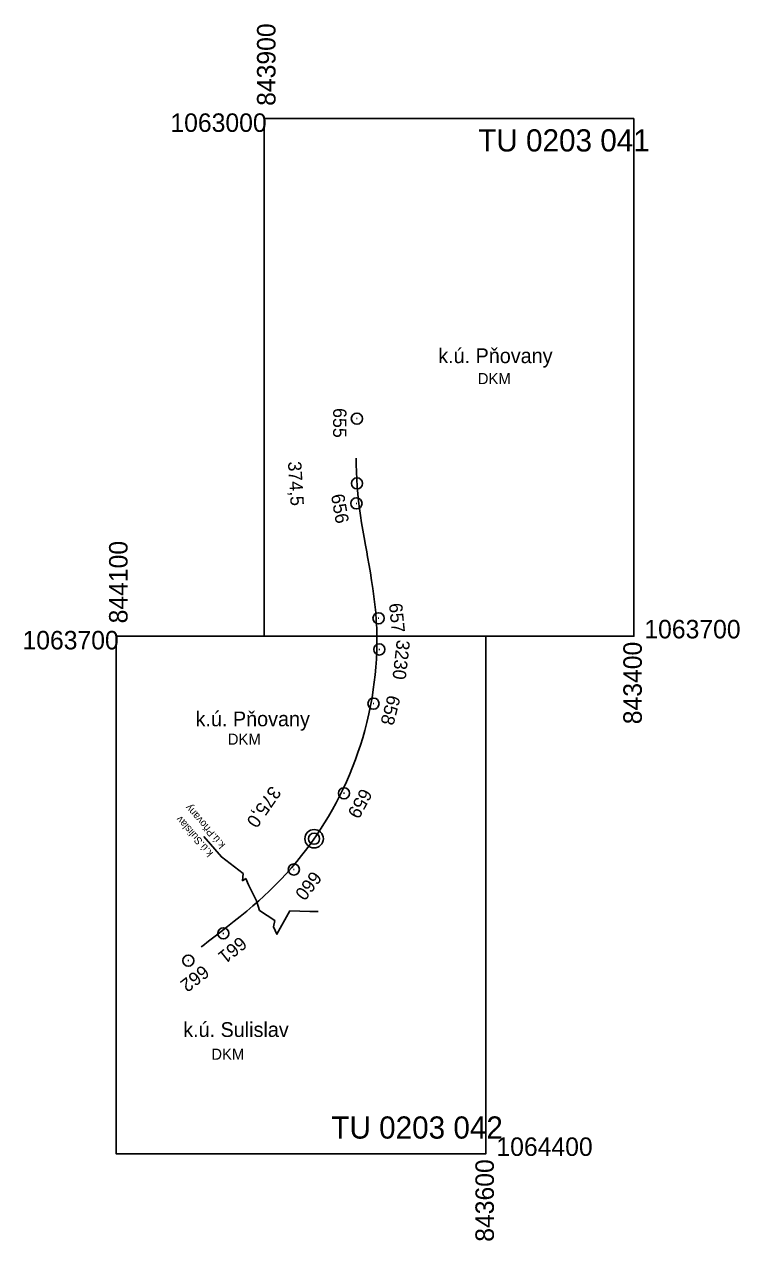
# Model space of a CAD drawing. Extents: x -867628 to -843257, y -1065611 to -1039859.
# Drawn here: x -844224 to -843257, y -1064518 to -1062872 of the extents above; entities that cross this region are included whole.
import ezdxf

# ---------------------------------------------------------------- set-up
doc = ezdxf.new("R2010")
doc.units = 0
for name, color, linetype in [('Vrstva 1', 7, 'Continuous'), ('Vrstva 10', 7, 'Continuous'), ('Vrstva 55', 7, 'Continuous'), ('Vrstva 62', 7, 'Continuous'), ('Vrstva 63', 7, 'Continuous'), ('Vrstva 7', 7, 'Continuous')]:
    doc.layers.add(name, color=color, linetype=linetype)

msp = doc.modelspace()

# ---------------------------------------------------------------- linework, layer by layer
at = {"layer": 'Vrstva 1'}
msp.add_lwpolyline([(-843775.2, -1063459.4), (-843775.2, -1063467.7), (-843775.1, -1063477.8), (-843774.7, -1063487.5), (-843774, -1063497.6), (-843773.1, -1063507.6), (-843772.1, -1063517.6), (-843770.8, -1063527.5), (-843769.5, -1063536.9), (-843768, -1063546.8), (-843766.4, -1063556.4), (-843764.7, -1063566.6), (-843762.9, -1063576.7), (-843761.2, -1063585.8), (-843760, -1063592.8), (-843757.9, -1063604.3), (-843756.2, -1063614.5), (-843754.5, -1063624.9), (-843752.9, -1063635.3), (-843751.4, -1063646.2), (-843750.1, -1063657.2), (-843749, -1063668.1), (-843748.2, -1063679), (-843747.6, -1063689.8), (-843747.3, -1063700.2), (-843747.3, -1063710.3), (-843747.5, -1063720.2), (-843748, -1063730.9), (-843748.8, -1063741.7), (-843749.7, -1063752.2), (-843750.9, -1063762.4), (-843752.3, -1063772.3), (-843754, -1063783.4), (-843756, -1063793.9), (-843758.3, -1063805.2), (-843761, -1063816.9), (-843763.8, -1063827.4), (-843766.6, -1063837.3), (-843769.7, -1063847.6), (-843773, -1063857.5), (-843776.4, -1063866.9), (-843780.4, -1063877.3), (-843784.5, -1063887.4), (-843788.6, -1063896.8), (-843793, -1063906.3), (-843797.3, -1063915.3), (-843802.6, -1063925.5), (-843807.5, -1063934.5), (-843812.9, -1063943.8), (-843818.2, -1063952.7), (-843823.5, -1063960.9), (-843829.6, -1063970.1), (-843835.9, -1063979.2), (-843842.1, -1063987.5), (-843849.2, -1063996.8), (-843855.8, -1064005), (-843862.9, -1064013.3), (-843870.1, -1064021.4), (-843877.4, -1064029.3), (-843884.8, -1064036.9), (-843892.7, -1064044.6), (-843900.3, -1064051.8), (-843907.1, -1064057.9), (-843915.1, -1064064.9), (-843923.4, -1064071.9), (-843932.1, -1064079.1), (-843940.4, -1064085.7), (-843949.5, -1064092.9), (-843958, -1064099.5), (-843965.9, -1064105.7), (-843974.9, -1064112.7), (-843982.7, -1064118.7), (-843984.8, -1064120.3)], dxfattribs=at)
at = {"layer": 'Vrstva 55'}
for points in [[(-843981.4, -1063971.1), (-843957.5, -1063998.5), (-843928.4, -1064021.2), (-843929.1, -1064030.8), (-843924.7, -1064027.6)], [(-843981.4, -1063971.1), (-843957.5, -1063998.5), (-843928.4, -1064021.2), (-843929.1, -1064030.8), (-843924.7, -1064027.6)], [(-843924.7, -1064027.6), (-843920.9, -1064036.4), (-843910, -1064058.1), (-843906.3, -1064071), (-843885.6, -1064084.8), (-843887.1, -1064093.1), (-843882.5, -1064103.2), (-843864.9, -1064071.7), (-843838.1, -1064072.2), (-843826.6, -1064072.5)], [(-843924.7, -1064027.6), (-843920.9, -1064036.4), (-843910, -1064058.1), (-843906.3, -1064071), (-843885.6, -1064084.8), (-843887.1, -1064093.1), (-843882.5, -1064103.2), (-843864.9, -1064071.7), (-843838.1, -1064072.2), (-843826.6, -1064072.5)]]:
    msp.add_lwpolyline(points, dxfattribs=at)
at = {"layer": 'Vrstva 62'}
for points in [[(-843400, -1063000), (-843400, -1063700), (-843900, -1063700), (-843900, -1063000)], [(-843600, -1063700), (-843600, -1064400), (-844100, -1064400), (-844100, -1063700)]]:
    msp.add_lwpolyline(points, close=True, dxfattribs=at)
at = {"layer": 'Vrstva 63'}
for p, q in [((-843774.9, -1063405.8), (-843773.9, -1063405.8)), ((-843775.5, -1063520.4), (-843774.5, -1063520.4)), ((-843745.7, -1063675.8), (-843744.7, -1063675.8)), ((-843744.6, -1063718), (-843743.6, -1063718)), ((-843752.5, -1063791.2), (-843751.5, -1063791.2)), ((-843792.4, -1063912.5), (-843791.4, -1063912.5)), ((-843860.2, -1064015.6), (-843859.2, -1064015.6)), ((-843955.5, -1064102), (-843954.5, -1064102)), ((-844002.8, -1064138.9), (-844001.8, -1064138.9))]:
    msp.add_line(p, q, dxfattribs=at)
for centre in [(-843774.4, -1063405.8), (-843775, -1063520.4), (-843745.2, -1063675.8), (-843744.1, -1063718), (-843752, -1063791.2), (-843791.9, -1063912.5), (-843859.7, -1064015.6), (-843955, -1064102), (-844002.3, -1064138.9)]:
    msp.add_circle(centre, 7.56, dxfattribs=at)
at = {"layer": 'Vrstva 7'}
for centre, radius in [((-843774.3, -1063493.4), 7.5), ((-843832.3, -1063974), 12.5), ((-843832.3, -1063974), 7.52)]:
    msp.add_circle(centre, radius, dxfattribs=at)

# ---------------------------------------------------------------- texts
at = {"layer": 'Vrstva 10'}
for p in [(-843611, -1063359.1), (-843949, -1063846.8), (-843971.3, -1064272.9)]:
    msp.add_text('DKM', height=15, dxfattribs=at).set_placement(p)
at = {"layer": 'Vrstva 55'}
for s, p in [('k.ú. Pňovany', (-843664.5, -1063330.7)), ('k.ú. Pňovany', (-843992.6, -1063821.9)), ('k.ú. Sulislav', (-844009.3, -1064242.1))]:
    msp.add_text(s, height=20, dxfattribs=at).set_placement(p)
for s, p in [('k.ú.Pňovany', (-843951.7, -1063981.9)), ('k.ú.Sulislav', (-843968.1, -1063993.1))]:
    msp.add_text(s, height=10, rotation=131.1696, dxfattribs=at).set_placement(p)
at = {"layer": 'Vrstva 62'}
for s, p in [('843900', (-843884.5, -1062982.7)), ('844100', (-844084.5, -1063682.7)), ('843400', (-843389.2, -1063819.1)), ('843600', (-843589.2, -1064519.1))]:
    msp.add_text(s, height=25, rotation=90, dxfattribs=at).set_placement(p)
for s, height, p in [('1063000', 25, (-844026.6, -1063017.9)), ('TU 0203 041', 30, (-843610.4, -1063044.4)), ('1063700', 25, (-843385.8, -1063703)), ('1063700', 25, (-844226.6, -1063717.9)), ('TU 0203 042', 30, (-843809, -1064379.6)), ('1064400', 25, (-843585.8, -1064403))]:
    msp.add_text(s, height=height, dxfattribs=at).set_placement(p)
at = {"layer": 'Vrstva 63'}
for s, rotation, p in [('655', 269.7096, (-843806.5, -1063391.4)), ('656', 280.057, (-843809.6, -1063509.2)), ('657', 275.6631, (-843731.2, -1063656.1)), ('3230', 263.4916, (-843720.4, -1063704.4)), ('658', 255.4554, (-843732.6, -1063778.6)), ('659', 241.3694, (-843768.4, -1063904.5)), ('660', 232.3614, (-843834.7, -1064016.3)), ('661', 218.7671, (-843932.4, -1064105.1)), ('662', 217.7695, (-843983.1, -1064143.8))]:
    msp.add_text(s, height=18, rotation=rotation, dxfattribs=at).set_placement(p)
at = {"layer": 'Vrstva 7'}
for s, rotation, p in [('374,5', 273.6126, (-843867.7, -1063464.1)), ('375,0', 235.2977, (-843890.3, -1063901.2))]:
    msp.add_text(s, height=18, rotation=rotation, dxfattribs=at).set_placement(p)

doc.saveas('drawing.dxf')
